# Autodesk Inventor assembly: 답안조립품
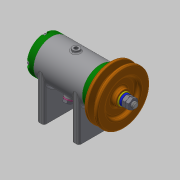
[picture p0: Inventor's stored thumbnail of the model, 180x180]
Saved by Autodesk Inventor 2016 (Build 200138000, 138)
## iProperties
Created: 2020-07
Part Number: 답안조립품
Document SubType Name: Assembly
Designer: user
Author: user
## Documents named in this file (15)
- C:\Users\user\Desktop\700706V1001\답안조립품.iam
- C:\Users\user\Desktop\700706V1001\본체.ipt
- C:\Users\user\Desktop\700706V1001\축.ipt
- C:\Users\user\Desktop\700706V1001\베어링 6002.ipt
- C:\Users\user\Desktop\700706V1001\뒤커버.ipt
- C:\Users\user\Desktop\700706V1001\앞커버.ipt
- C:\Users\user\Desktop\700706V1001\키 3x3x12.ipt
- C:\Users\user\Desktop\700706V1001\오일 실 15 25 7.ipt
- C:\Users\user\Desktop\700706V1001\V벨트풀리.ipt
- C:\Users\user\Desktop\700706V1001\와셔 8x17.ipt
- C:\Users\user\Desktop\700706V1001\스프링와셔 8.ipt
- C:\Users\user\Desktop\700706V1001\너트 M8.ipt
- C:\Users\user\Desktop\700706V1001\와셔 6x11.5.ipt
- C:\Users\user\Desktop\700706V1001\볼트 M6x8.ipt
- C:\Users\user\Desktop\700706V1001\볼트 M4x12.ipt
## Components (1 placed, 1 different names)
1. V벨트풀리:1
